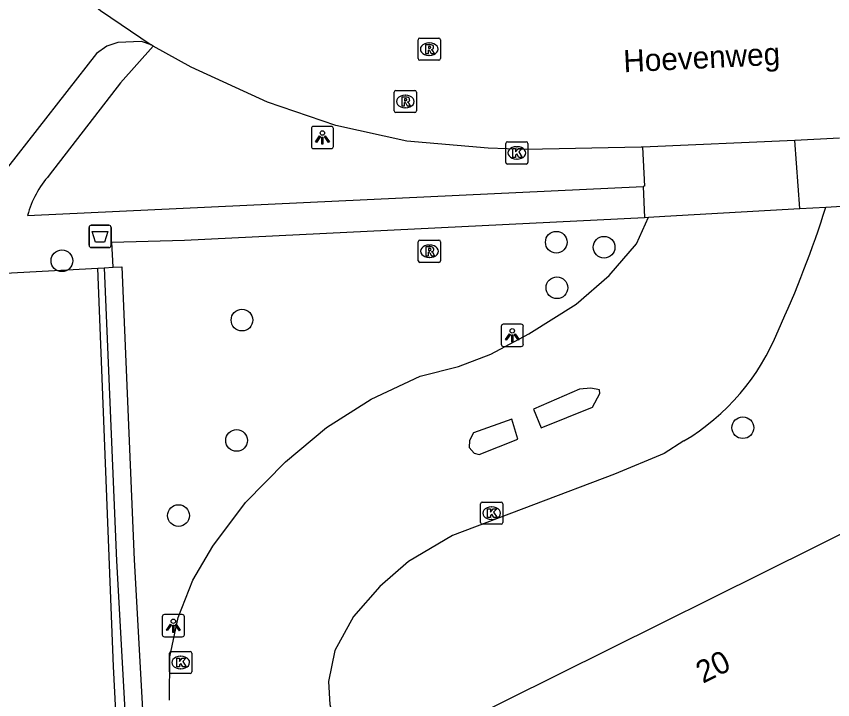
# Model space of a CAD drawing. Extents: x 157692 to 159670, y 381454 to 383289.
# Drawn here: x 157922.89 to 157959.64, y 381562 to 381592.77 of the extents above; entities that cross this region are included whole.
import ezdxf

# ---------------------------------------------------------------- set-up
doc = ezdxf.new("R2010")
doc.units = 0
for name, color, linetype in [('IMGEO_Afvalbak', 7, 'Continuous'), ('IMGEO_Boom', 7, 'Continuous'), ('IMGEO_Haag', 7, 'Continuous'), ('IMGEO_Kolk', 7, 'Continuous'), ('IMGEO_Lichtpunt', 7, 'Continuous'), ('IMGEO_Openbare_ruimte_label', 7, 'Continuous'), ('IMGEO_Pand', 7, 'Continuous'), ('IMGEO_Pand_nummerreeks', 7, 'Continuous'), ('IMGEO_Parkeervlak_open', 7, 'Continuous'), ('IMGEO_Rijbaan_lokaal_gesloten', 7, 'Continuous'), ('IMGEO_Rijbaan_lokaal_open', 7, 'Continuous'), ('IMGEO_Rioolput', 7, 'Continuous'), ('IMGEO_Voetpad_open', 7, 'Continuous')]:
    doc.layers.add(name, color=color, linetype=linetype)

msp = doc.modelspace()

# ---------------------------------------------------------------- linework, layer by layer
at = {"layer": 'IMGEO_Afvalbak'}
for p, q in [((157926.164, 381582.459), (157926.164, 381583.259)), ((157926.164, 381583.259), (157926.164, 381582.459)), ((157926.264, 381583.359), (157927.054, 381583.359)), ((157927.054, 381583.359), (157926.264, 381583.359)), ((157927.154, 381583.259), (157927.154, 381582.459)), ((157927.154, 381582.459), (157927.154, 381583.259)), ((157927.054, 381582.359), (157926.264, 381582.359)), ((157926.264, 381582.359), (157927.054, 381582.359))]:
    msp.add_line(p, q, dxfattribs=at)
msp.add_lwpolyline([(157926.307, 381583.073), (157927.011, 381583.073), (157926.862, 381582.603), (157926.456, 381582.603), (157926.307, 381583.073)], dxfattribs=at)
for centre, start, end in [((157926.264, 381583.259), 90, 180), ((157926.264, 381583.259), 90, 180), ((157927.054, 381583.259), 0, 90), ((157927.054, 381583.259), 360, 90), ((157926.264, 381582.459), 180, 270), ((157926.264, 381582.459), 180, 270), ((157927.054, 381582.459), 270, 0), ((157927.054, 381582.459), 270, 0)]:
    msp.add_arc(centre, 0.1, start, end, dxfattribs=at)
at = {"layer": 'IMGEO_Boom'}
for centre in [(157947.199, 381582.598), (157949.349, 381582.373), (157924.941, 381581.762), (157947.228, 381580.549), (157933.047, 381579.092), (157955.597, 381574.247), (157932.805, 381573.672), (157930.189, 381570.287)]:
    msp.add_circle(centre, 0.489, dxfattribs=at)
at = {"layer": 'IMGEO_Haag'}
for points in [[(157926.841, 381581.45), (157927.395, 381568.252), (157929.071, 381538.037), (157929.487, 381527.095), (157929.643, 381523.008), (157918.87, 381522.361), (157913.803, 381522.136), (157911.996, 381561.898), (157910.985, 381579.553), (157910.843, 381582.033), (157910.937, 381583.062), (157920.188, 381595.274)], [(157927.24, 381581.471), (157927.64, 381581.488), (157928.195, 381568.29), (157929.871, 381538.075), (157930.287, 381527.125), (157930.457, 381522.677)]]:
    msp.add_lwpolyline(points, dxfattribs=at)
at = {"layer": 'IMGEO_Kolk'}
for p, q in [((157944.919, 381586.192), (157944.919, 381587.044)), ((157944.994, 381587.118), (157945.846, 381587.118)), ((157945.92, 381587.044), (157945.92, 381586.192)), ((157945.407, 381586.898), (157945.432, 381586.898)), ((157945.43, 381586.338), (157945.405, 381586.338)), ((157945.846, 381586.118), (157944.994, 381586.118)), ((157943.786, 381569.97), (157943.786, 381570.822)), ((157943.861, 381570.896), (157944.713, 381570.896)), ((157944.787, 381570.822), (157944.787, 381569.97)), ((157944.274, 381570.676), (157944.299, 381570.676)), ((157944.297, 381570.116), (157944.272, 381570.116)), ((157944.713, 381569.896), (157943.861, 381569.896)), ((157929.862, 381564.172), (157930.714, 381564.172)), ((157929.787, 381563.246), (157929.787, 381564.098)), ((157930.275, 381563.952), (157930.3, 381563.952)), ((157930.788, 381564.098), (157930.788, 381563.246)), ((157930.714, 381563.172), (157929.862, 381563.172)), ((157930.298, 381563.392), (157930.273, 381563.392))]:
    msp.add_line(p, q, dxfattribs=at)
for points in [[(157944.919, 381586.192), (157944.919, 381587.044)], [(157944.994, 381587.118), (157945.846, 381587.118)], [(157945.92, 381587.044), (157945.92, 381586.192)], [(157945.24, 381586.818), (157945.363, 381586.818), (157945.363, 381586.667), (157945.493, 381586.818), (157945.657, 381586.818), (157945.511, 381586.667), (157945.664, 381586.418), (157945.512, 381586.418), (157945.427, 381586.582), (157945.363, 381586.515), (157945.363, 381586.418), (157945.24, 381586.418), (157945.24, 381586.818)], [(157945.846, 381586.118), (157944.994, 381586.118)], [(157943.786, 381569.97), (157943.786, 381570.822)], [(157943.861, 381570.896), (157944.713, 381570.896)], [(157944.787, 381570.822), (157944.787, 381569.97)], [(157944.107, 381570.596), (157944.23, 381570.596), (157944.23, 381570.445), (157944.36, 381570.596), (157944.524, 381570.596), (157944.378, 381570.445), (157944.531, 381570.196), (157944.379, 381570.196), (157944.294, 381570.36), (157944.23, 381570.293), (157944.23, 381570.196), (157944.107, 381570.196), (157944.107, 381570.596)], [(157944.713, 381569.896), (157943.861, 381569.896)], [(157929.862, 381564.172), (157930.714, 381564.172)], [(157929.787, 381563.246), (157929.787, 381564.098)], [(157930.108, 381563.872), (157930.231, 381563.872), (157930.231, 381563.721), (157930.361, 381563.872), (157930.525, 381563.872), (157930.379, 381563.721), (157930.532, 381563.472), (157930.38, 381563.472), (157930.295, 381563.636), (157930.231, 381563.569), (157930.231, 381563.472), (157930.108, 381563.472), (157930.108, 381563.872)], [(157930.788, 381564.098), (157930.788, 381563.246)], [(157930.714, 381563.172), (157929.862, 381563.172)]]:
    msp.add_lwpolyline(points, dxfattribs=at)
for centre, start, end in [((157944.996, 381587.042), 91.552, 178.448), ((157944.996, 381587.042), 91.552, 178.448), ((157945.844, 381587.042), 1.552, 88.448), ((157945.844, 381587.042), 1.552, 88.448), ((157944.996, 381586.194), 181.552, 268.448), ((157944.996, 381586.194), 181.552, 268.448), ((157945.844, 381586.194), 271.552, 358.448), ((157945.844, 381586.194), 271.552, 358.448), ((157943.863, 381570.82), 91.552, 178.448), ((157943.863, 381570.82), 91.552, 178.448), ((157944.711, 381570.82), 1.552, 88.448), ((157944.711, 381570.82), 1.552, 88.448), ((157943.863, 381569.972), 181.552, 268.448), ((157943.863, 381569.972), 181.552, 268.448), ((157944.711, 381569.972), 271.552, 358.448), ((157944.711, 381569.972), 271.552, 358.448), ((157929.864, 381564.096), 91.552, 178.448), ((157929.864, 381564.096), 91.552, 178.448), ((157930.712, 381564.096), 1.552, 88.448), ((157930.712, 381564.096), 1.552, 88.448), ((157929.864, 381563.248), 181.552, 268.448), ((157929.864, 381563.248), 181.552, 268.448), ((157930.712, 381563.248), 271.552, 358.448), ((157930.712, 381563.248), 271.552, 358.448)]:
    msp.add_arc(centre, 0.0765, start, end, dxfattribs=at)
for centre, major_axis, ratio, start_param, end_param in [((157945.406, 381586.618), (-0.387, 0.002), 0.722429, 4.712389, 7.853982), ((157945.431, 381586.618), (-0.39, 0.002), 0.717154, 1.570796, 4.712389), ((157944.273, 381570.396), (-0.387, 0.002), 0.722429, 4.712389, 7.853982), ((157944.298, 381570.396), (-0.39, 0.002), 0.717154, 1.570796, 4.712389), ((157930.274, 381563.672), (-0.387, 0.002), 0.722429, 4.712389, 7.853982), ((157930.299, 381563.672), (-0.39, 0.002), 0.717154, 1.570796, 4.712389)]:
    msp.add_ellipse(centre, major_axis=major_axis, ratio=ratio, start_param=start_param, end_param=end_param, dxfattribs=at)
at = {"layer": 'IMGEO_Lichtpunt'}
for p, q in [((157936.17, 381587.718), (157936.17, 381586.911)), ((157936.17, 381587.718), (157936.17, 381586.911)), ((157937.072, 381587.813), (157936.264, 381587.813)), ((157937.072, 381587.813), (157936.264, 381587.813)), ((157937.166, 381586.911), (157937.166, 381587.718)), ((157937.166, 381586.911), (157937.166, 381587.718)), ((157936.264, 381586.817), (157937.072, 381586.817)), ((157936.264, 381586.817), (157937.072, 381586.817)), ((157945.62, 381578.904), (157944.812, 381578.904)), ((157945.62, 381578.904), (157944.812, 381578.904)), ((157944.718, 381578.809), (157944.718, 381578.002)), ((157944.718, 381578.809), (157944.718, 381578.002)), ((157945.714, 381578.002), (157945.714, 381578.809)), ((157945.714, 381578.002), (157945.714, 381578.809)), ((157944.812, 381577.908), (157945.62, 381577.908)), ((157944.812, 381577.908), (157945.62, 381577.908)), ((157929.457, 381565.733), (157929.457, 381564.926)), ((157929.457, 381565.733), (157929.457, 381564.926)), ((157930.359, 381565.828), (157929.551, 381565.828)), ((157930.359, 381565.828), (157929.551, 381565.828)), ((157930.453, 381564.926), (157930.453, 381565.733)), ((157930.453, 381564.926), (157930.453, 381565.733)), ((157929.551, 381564.832), (157930.359, 381564.832)), ((157929.551, 381564.832), (157930.359, 381564.832))]:
    msp.add_line(p, q, dxfattribs=at)
for points in [[(157936.544, 381587.382), (157936.583, 381587.354), (157936.395, 381587.092), (157936.357, 381587.119), (157936.544, 381587.382)], [(157936.646, 381587.334), (157936.693, 381587.334), (157936.693, 381587.012), (157936.646, 381587.012), (157936.646, 381587.334)], [(157936.756, 381587.354), (157936.794, 381587.381), (157936.981, 381587.119), (157936.942, 381587.091), (157936.756, 381587.354)], [(157945.092, 381578.473), (157945.131, 381578.445), (157944.943, 381578.183), (157944.905, 381578.21), (157945.092, 381578.473)], [(157945.304, 381578.445), (157945.342, 381578.472), (157945.529, 381578.21), (157945.49, 381578.182), (157945.304, 381578.445)], [(157945.194, 381578.425), (157945.241, 381578.425), (157945.241, 381578.103), (157945.194, 381578.103), (157945.194, 381578.425)], [(157929.831, 381565.397), (157929.87, 381565.369), (157929.682, 381565.107), (157929.644, 381565.134), (157929.831, 381565.397)], [(157929.933, 381565.349), (157929.98, 381565.349), (157929.98, 381565.027), (157929.933, 381565.027), (157929.933, 381565.349)], [(157930.043, 381565.369), (157930.081, 381565.396), (157930.268, 381565.134), (157930.229, 381565.106), (157930.043, 381565.369)]]:
    msp.add_lwpolyline(points, dxfattribs=at)
for centre in [(157936.669, 381587.516), (157945.217, 381578.607), (157929.956, 381565.531)]:
    msp.add_circle(centre, 0.0994, dxfattribs=at)
for centre, start, end in [((157936.264, 381587.718), 90, 180), ((157936.264, 381587.718), 90, 180), ((157937.072, 381587.718), 0, 90), ((157937.072, 381587.718), 0, 90), ((157936.264, 381586.911), 180, 270), ((157936.264, 381586.911), 180, 270), ((157937.072, 381586.911), 270, 0), ((157937.072, 381586.911), 270, 360), ((157944.812, 381578.809), 90, 180), ((157944.812, 381578.809), 90, 180), ((157945.62, 381578.809), 0, 90), ((157945.62, 381578.809), 0, 90), ((157944.812, 381578.002), 180, 270), ((157944.812, 381578.002), 180, 270), ((157945.62, 381578.002), 270, 0), ((157945.62, 381578.002), 270, 360), ((157929.551, 381565.733), 90, 180), ((157929.551, 381565.733), 90, 180), ((157930.359, 381565.733), 0, 90), ((157930.359, 381565.733), 0, 90), ((157929.551, 381564.926), 180, 270), ((157929.551, 381564.926), 180, 270), ((157930.359, 381564.926), 270, 0), ((157930.359, 381564.926), 270, 360)]:
    msp.add_arc(centre, 0.0946, start, end, dxfattribs=at)
at = {"layer": 'IMGEO_Pand'}
msp.add_lwpolyline([(157944.012, 381552.206), (157940.297, 381559.668), (157965.864, 381572.367), (157967.892, 381568.285), (157977.928, 381573.254), (157990.462, 381548.606), (157959.887, 381533.401), (157957.749, 381537.478), (157951.566, 381549.266), (157946.672, 381546.863)], dxfattribs=at)
at = {"layer": 'IMGEO_Parkeervlak_open'}
msp.add_lwpolyline([(157911.146, 381580.299), (157912.461, 381554.564), (157913.843, 381524.592), (157914.067, 381522.921), (157914.656, 381522.414), (157918.836, 381522.563), (157919.068, 381522.574), (157923.982, 381522.808), (157928.783, 381523.036), (157929.213, 381523.146), (157928.382, 381541.773), (157927.269, 381563.492), (157926.563, 381581.435)], dxfattribs=at)
at = {"layer": 'IMGEO_Rijbaan_lokaal_gesloten'}
for points in [[(157921.704, 381597.546), (157924.075, 381595.18), (157926.673, 381593.026), (157928.952, 381591.478)], [(157929.051, 381591.423), (157928.952, 381591.478)], [(157951.074, 381586.874), (157951.019, 381586.872), (157945.839, 381586.771), (157944.13, 381586.826), (157940.474, 381587.149), (157937.272, 381587.854), (157934.191, 381588.901), (157930.756, 381590.478), (157929.051, 381591.423)], [(157957.932, 381587.181), (157951.074, 381586.874)], [(157959.949, 381587.281), (157957.932, 381587.181)]]:
    msp.add_lwpolyline(points, dxfattribs=at)
at = {"layer": 'IMGEO_Rijbaan_lokaal_open'}
for points in [[(157928.952, 381591.478), (157928.522, 381591.637), (157927.456, 381591.588), (157926.958, 381591.42), (157926.49, 381591.102), (157922.484, 381585.955), (157922.087, 381585.134), (157921.843, 381584.271), (157921.726, 381583.494), (157921.813, 381581.179)], [(157958.16, 381584.119), (157957.932, 381587.181)], [(157951.074, 381586.874), (157951.164, 381585.115), (157951.103, 381585.112)], [(157951.103, 381585.112), (157951.17, 381583.715)], [(157951.353, 381583.724), (157952.091, 381583.765), (157958.16, 381584.119)], [(157958.16, 381584.119), (157959.334, 381584.178)], [(157929.777, 381561.982), (157929.797, 381563.926), (157930.172, 381565.696), (157930.834, 381567.374), (157931.74, 381568.914), (157933.206, 381570.874), (157935.003, 381572.702), (157936.859, 381574.253), (157938.859, 381575.531), (157941.068, 381576.562), (157942.792, 381577.004), (157944.25, 381577.561), (157945.969, 381578.478), (157948.096, 381579.807), (157949.577, 381581.099), (157950.814, 381582.528), (157951.353, 381583.724)], [(157951.17, 381583.715), (157951.353, 381583.724)], [(157948.829, 381575.165), (157949.151, 381575.788), (157949.142, 381575.949), (157948.759, 381576.025), (157948.244, 381575.985), (157946.179, 381575.081), (157946.517, 381574.247), (157948.829, 381575.165)], [(157945.467, 381573.724), (157945.189, 381574.637), (157943.465, 381574.011), (157943.289, 381573.677), (157943.275, 381573.353), (157943.506, 381573.096), (157943.724, 381573.043), (157945.467, 381573.724)], [(157952.938, 381573.65), (157952.059, 381573.078), (157949.823, 381572.153), (157942.53, 381569.39), (157940.545, 381568.221), (157939.249, 381567.09), (157938.072, 381565.751), (157937.23, 381564.214), (157936.942, 381562.816), (157937, 381561.783), (157937.455, 381560.211), (157938.578, 381557.511), (157941.476, 381552.428), (157942.219, 381551.887), (157942.784, 381551.811), (157943.512, 381551.916), (157944.012, 381552.206)]]:
    msp.add_lwpolyline(points, dxfattribs=at)
for centre, radius, start, end in [((157913.477, 381598.654), 48.087, 335.3686, 342.4805), ((157947.714, 381582.428), 10.215, 300.7605, 338.0654)]:
    msp.add_arc(centre, radius, start, end, dxfattribs=at)
at = {"layer": 'IMGEO_Rioolput'}
for p, q in [((157940.977, 381590.864), (157940.977, 381591.716)), ((157941.052, 381591.79), (157941.904, 381591.79)), ((157941.978, 381591.716), (157941.978, 381590.864)), ((157941.465, 381591.57), (157941.49, 381591.57)), ((157941.488, 381591.01), (157941.463, 381591.01)), ((157941.904, 381590.79), (157941.052, 381590.79)), ((157939.9, 381588.506), (157939.9, 381589.358)), ((157939.975, 381589.432), (157940.827, 381589.432)), ((157940.388, 381589.212), (157940.413, 381589.212)), ((157940.901, 381589.358), (157940.901, 381588.506)), ((157940.827, 381588.432), (157939.975, 381588.432)), ((157940.411, 381588.652), (157940.386, 381588.652)), ((157940.986, 381581.764), (157940.986, 381582.616)), ((157941.061, 381582.69), (157941.913, 381582.69)), ((157941.987, 381582.616), (157941.987, 381581.764)), ((157941.474, 381582.47), (157941.499, 381582.47)), ((157941.497, 381581.91), (157941.472, 381581.91)), ((157941.913, 381581.69), (157941.061, 381581.69))]:
    msp.add_line(p, q, dxfattribs=at)
for points in [[(157940.977, 381590.864), (157940.977, 381591.716)], [(157941.052, 381591.79), (157941.904, 381591.79)], [(157941.978, 381591.716), (157941.978, 381590.864)], [(157941.566, 381591.488), (157941.314, 381591.49), (157941.314, 381591.09)], [(157941.492, 381591.409), (157941.438, 381591.409), (157941.438, 381591.328)], [(157941.314, 381591.09), (157941.438, 381591.09), (157941.438, 381591.252), (157941.449, 381591.252)], [(157941.438, 381591.328), (157941.49, 381591.328)], [(157941.496, 381591.223), (157941.567, 381591.09), (157941.707, 381591.09), (157941.642, 381591.216)], [(157941.904, 381590.79), (157941.052, 381590.79)], [(157939.9, 381588.506), (157939.9, 381589.358)], [(157939.975, 381589.432), (157940.827, 381589.432)], [(157940.489, 381589.13), (157940.237, 381589.132), (157940.237, 381588.732)], [(157940.901, 381589.358), (157940.901, 381588.506)], [(157940.237, 381588.732), (157940.361, 381588.732), (157940.361, 381588.894), (157940.372, 381588.894)], [(157940.415, 381589.051), (157940.361, 381589.051), (157940.361, 381588.97)], [(157940.361, 381588.97), (157940.413, 381588.97)], [(157940.419, 381588.865), (157940.49, 381588.732), (157940.63, 381588.732), (157940.565, 381588.858)], [(157940.827, 381588.432), (157939.975, 381588.432)], [(157940.986, 381581.764), (157940.986, 381582.616)], [(157941.061, 381582.69), (157941.913, 381582.69)], [(157941.987, 381582.616), (157941.987, 381581.764)], [(157941.575, 381582.388), (157941.323, 381582.39), (157941.323, 381581.99)], [(157941.323, 381581.99), (157941.447, 381581.99), (157941.447, 381582.152), (157941.458, 381582.152)], [(157941.501, 381582.309), (157941.447, 381582.309), (157941.447, 381582.228)], [(157941.447, 381582.228), (157941.499, 381582.228)], [(157941.505, 381582.123), (157941.576, 381581.99), (157941.716, 381581.99), (157941.651, 381582.116)], [(157941.913, 381581.69), (157941.061, 381581.69)]]:
    msp.add_lwpolyline(points, dxfattribs=at)
for centre, radius, start, end in [((157941.054, 381591.714), 0.0765, 91.552, 178.448), ((157941.054, 381591.714), 0.0765, 91.552, 178.448), ((157941.902, 381591.714), 0.0765, 1.552, 88.448), ((157941.902, 381591.714), 0.0765, 1.552, 88.448), ((157941.498, 381591.313), 0.0964, 77.0061, 93.1865), ((157941.512, 381591.37), 0.0378, 276.6634, 79.6772), ((157941.565, 381591.378), 0.109, 350.3612, 89.416), ((157941.563, 381591.378), 0.112, 277.5842, 350.9817), ((157941.448, 381591.199), 0.0533, 26.0293, 88.6989), ((157941.474, 381591.517), 0.19, 274.7715, 282.9687), ((157941.547, 381591.163), 0.108, 29.5134, 73.7905), ((157941.054, 381590.866), 0.0765, 181.552, 268.448), ((157941.054, 381590.866), 0.0765, 181.552, 268.448), ((157941.902, 381590.866), 0.0765, 271.552, 358.448), ((157941.902, 381590.866), 0.0765, 271.552, 358.448), ((157939.977, 381589.356), 0.0765, 91.552, 178.448), ((157939.977, 381589.356), 0.0765, 91.552, 178.448), ((157940.488, 381589.02), 0.109, 350.3612, 89.416), ((157940.825, 381589.356), 0.0765, 1.552, 88.448), ((157940.825, 381589.356), 0.0765, 1.552, 88.448), ((157940.371, 381588.841), 0.0533, 26.0293, 88.6989), ((157940.397, 381589.159), 0.19, 274.7715, 282.9687), ((157940.421, 381588.955), 0.0964, 77.0061, 93.1865), ((157940.435, 381589.012), 0.0378, 276.6634, 79.6772), ((157940.486, 381589.02), 0.112, 277.5842, 350.9817), ((157940.47, 381588.805), 0.108, 29.5134, 73.7905), ((157939.977, 381588.508), 0.0765, 181.552, 268.448), ((157939.977, 381588.508), 0.0765, 181.552, 268.448), ((157940.825, 381588.508), 0.0765, 271.552, 358.448), ((157940.825, 381588.508), 0.0765, 271.552, 358.448), ((157941.063, 381582.614), 0.0765, 91.552, 178.448), ((157941.063, 381582.614), 0.0765, 91.552, 178.448), ((157941.911, 381582.614), 0.0765, 1.552, 88.448), ((157941.911, 381582.614), 0.0765, 1.552, 88.448), ((157941.457, 381582.099), 0.0533, 26.0293, 88.6989), ((157941.483, 381582.417), 0.19, 274.7715, 282.9687), ((157941.507, 381582.213), 0.0964, 77.0061, 93.1865), ((157941.521, 381582.27), 0.0378, 276.6634, 79.6772), ((157941.574, 381582.278), 0.109, 350.3612, 89.416), ((157941.572, 381582.278), 0.112, 277.5842, 350.9817), ((157941.556, 381582.063), 0.108, 29.5134, 73.7905), ((157941.063, 381581.766), 0.0765, 181.552, 268.448), ((157941.063, 381581.766), 0.0765, 181.552, 268.448), ((157941.911, 381581.766), 0.0765, 271.552, 358.448), ((157941.911, 381581.766), 0.0765, 271.552, 358.448)]:
    msp.add_arc(centre, radius, start, end, dxfattribs=at)
for centre, major_axis, ratio, start_param, end_param in [((157941.464, 381591.29), (-0.387, 0.002), 0.722429, 4.712389, 7.853982), ((157941.489, 381591.29), (-0.39, 0.002), 0.717154, 1.570796, 4.712389), ((157940.387, 381588.932), (-0.387, 0.002), 0.722429, 4.712389, 7.853982), ((157940.412, 381588.932), (-0.39, 0.002), 0.717154, 1.570796, 4.712389), ((157941.473, 381582.19), (-0.387, 0.002), 0.722429, 4.712389, 7.853982), ((157941.498, 381582.19), (-0.39, 0.002), 0.717154, 1.570796, 4.712389)]:
    msp.add_ellipse(centre, major_axis=major_axis, ratio=ratio, start_param=start_param, end_param=end_param, dxfattribs=at)
at = {"layer": 'IMGEO_Voetpad_open'}
for points in [[(157929.051, 381591.423), (157927.572, 381589.767), (157924.372, 381585.613)], [(157923.392, 381583.807), (157951.103, 381585.112)], [(157959.334, 381584.178), (157960.05, 381584.214), (157972.603, 381584.848)], [(157927.24, 381581.471), (157927.193, 381582.602), (157930.46, 381582.69), (157951.17, 381583.715)], [(157921.813, 381581.179), (157926.563, 381581.435)], [(157926.563, 381581.435), (157926.841, 381581.45)], [(157926.841, 381581.45), (157927.24, 381581.471)]]:
    msp.add_lwpolyline(points, dxfattribs=at)
msp.add_arc((157927.684, 381582.647), 4.446, 138.1528, 164.8755, dxfattribs=at)

# ---------------------------------------------------------------- texts
at = {"layer": 'IMGEO_Openbare_ruimte_label'}
msp.add_text('Hoevenweg', height=1, rotation=2.8081, dxfattribs=at).set_placement((157950.241, 381590.247))
at = {"layer": 'IMGEO_Pand_nummerreeks'}
msp.add_text('20', height=1, rotation=26.4134, dxfattribs=at).set_placement((157953.802, 381562.714))

doc.saveas('drawing.dxf')
